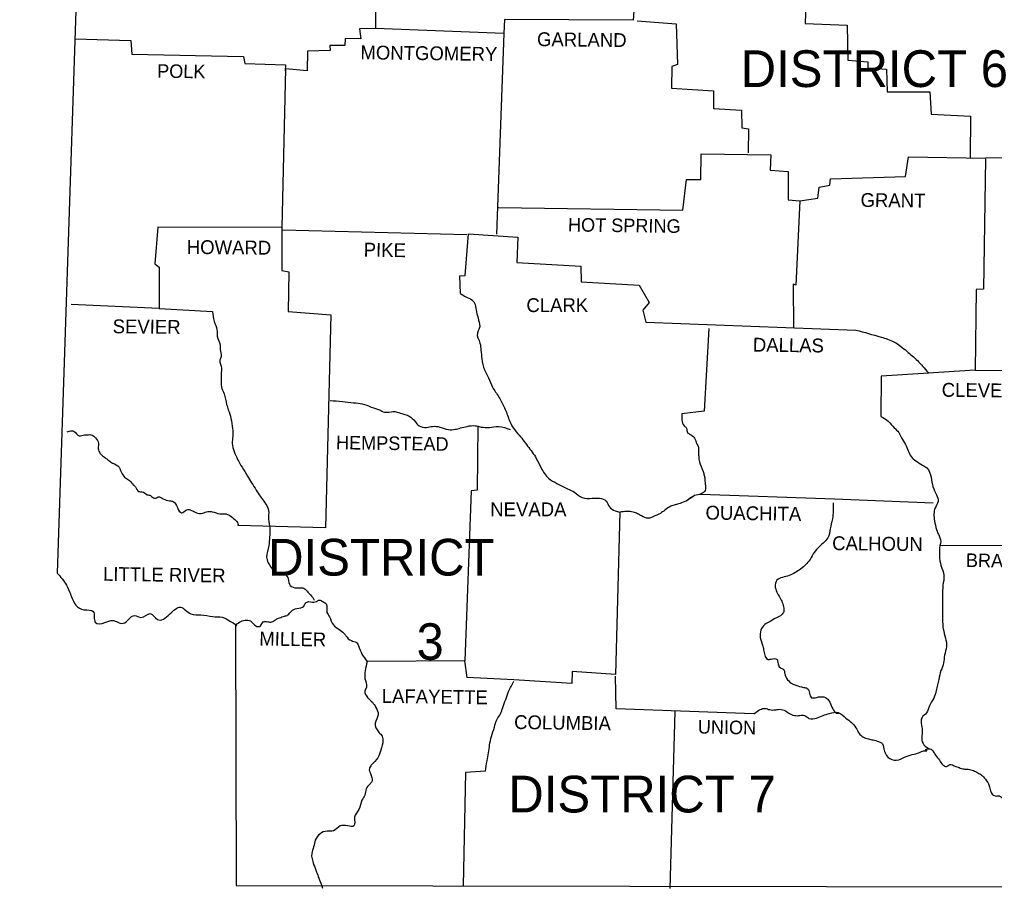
# Model space of a CAD drawing. Extents: x -42408 to 34530, y -43140 to 20491.
# Drawn here: x 1640 to 3155, y -35715 to -34364 of the extents above; entities that cross this region are included whole.
import ezdxf

# ---------------------------------------------------------------- set-up
doc = ezdxf.new("R2010")
doc.units = 0
for name, color, linetype in [('1', 7, 'Continuous'), ('2', 7, 'Continuous'), ('3', 7, 'Continuous')]:
    doc.layers.add(name, color=color, linetype=linetype)

msp = doc.modelspace()

# ---------------------------------------------------------------- linework, layer by layer
at = {"layer": '1'}
for points in [[(1640, -33034), (1743.7, -33866.1), (1698.6, -35224.4)], [(2194.3, -34085.9), (2193.3, -34378.7), (2168.2, -34379.2), (2170.2, -34394.3), (2146.2, -34393.8), (2145.7, -34404.8), (2122.2, -34404.8), (2122.7, -34412.8), (2087.6, -34413.8), (2087.1, -34444.3), (2053.1, -34441.3), (2047.6, -34687.7), (1854.8, -34687.2), (1850.3, -34744.2), (1857.3, -34749.2), (1856.8, -34813.3), (1720.1, -34807.3)], [(2762, -34306.2), (2598.3, -34301.1), (2593.8, -34365.7), (2393.5, -34364.7), (2392.5, -34386.3)], [(2806.6, -34304.6), (2862.7, -34308.2), (2860.6, -34370.7), (2926.2, -34373.2), (2927.2, -34427.8), (2958.3, -34430.3), (2958.3, -34439.8), (2987.3, -34441.8), (2988.3, -34476.9), (3054.4, -34476.9), (3056.4, -34511.4), (3117.5, -34514.4), (3117, -34579.5)], [(2599.8, -34366.7), (2660.4, -34371.2), (2662.4, -34434.3), (2653.9, -34437.3), (2652.9, -34470.9), (2718.5, -34475.4), (2718.5, -34502.9), (2762, -34505.4), (2762.5, -34533), (2773, -34534.5), (2772.5, -34571.5)], [(2392.5, -34386.3), (2193.3, -34378.7)], [(2392.5, -34386.3), (2381, -34698.2)], [(1726.1, -34394.3), (1812.8, -34397.3), (1814.8, -34418.3), (1988, -34421.8), (1990, -34432.8), (2053.1, -34434.8), (2052.6, -34444.3)], [(3714.3, -34521.9), (3525, -34516.9), (3524, -34578.5), (3141, -34580)], [(2384.5, -34656.6), (2670.9, -34660.6), (2676.4, -34613.1), (2698.9, -34613.1), (2699.4, -34573), (2807.6, -34574.5), (2806.6, -34598.5), (2834.6, -34600.5), (2834.6, -34644.6), (2852.6, -34646.1)], [(2852.6, -34646.1), (2880.7, -34642.1), (2882.7, -34625.1), (2899.2, -34622.1), (2900.2, -34612.1), (3016.9, -34608.6), (3021.4, -34578), (3141, -34580)], [(3141, -34581), (3138, -34783.3), (3126.5, -34783.8), (3125, -34909.5)], [(2852.6, -34646.1), (2846.6, -34777.3), (2842.1, -34775.8), (2842.6, -34843.9)], [(2047.6, -34687.7), (2047.6, -34754.2), (2058.6, -34756.3), (2057.6, -34818.3), (2123.7, -34823.3), (2115.7, -35154.3), (1979.5, -35150.8)], [(2048.6, -34691.2), (2334.9, -34698.7)], [(2325.4, -34790.3), (2324.4, -34762.8), (2332.4, -34762.3), (2337.5, -34697.7), (2414.6, -34702.7), (2412.6, -34742.2), (2512.2, -34747.7), (2512.7, -34771.8), (2602.8, -34777.3), (2618.3, -34804.3), (2608.8, -34816.3), (2613.3, -34834.9), (2939.8, -34846.9)], [(1856.8, -34813.3), (1939.9, -34818.3)], [(2711.4, -34844.4), (2703.9, -34973), (2669.4, -34977)], [(3052.9, -34914), (2978.8, -34918.5), (2978.3, -34981.1)], [(3125, -34909.5), (3051.9, -34914)], [(3125, -34909.5), (3302.2, -34910.5)], [(2352, -34996.1), (2351, -35095.7), (2342, -35096.7), (2331.9, -35360.6)], [(2698.9, -35101.7), (2906.2, -35109.2), (3059.9, -35115.2)], [(2572.8, -35129.8), (2566.3, -35382.1), (2498.7, -35377.6), (2498.2, -35396.1), (2408, -35390.6)], [(3069.9, -35181.8), (3296.2, -35181.3)], [(1975.5, -35305), (1976.5, -35710), (3811.4, -35713)], [(2408, -35390.6), (2335.4, -35386.6), (2331.9, -35360.6), (2180.2, -35362.1)], [(2781, -35443.2), (2567.3, -35435.2), (2566.3, -35384.6)], [(2658.4, -35439.7), (2650.4, -35714.5)], [(2364, -35532.3), (2332.9, -35534.3), (2329.4, -35710.5)]]:
    msp.add_lwpolyline(points, dxfattribs=at)
for points in [[(2325.4, -34790.3), (2333.4, -34795.3), (2343, -34799.8), (2348, -34807.3), (2350, -34818.8), (2353.5, -34831.4), (2354.5, -34844.4), (2351.5, -34851.4), (2355.5, -34867.4), (2357, -34878.4), (2358.5, -34891.4), (2362.5, -34909), (2369, -34921), (2375, -34935.5), (2385, -34951), (2393.5, -34968), (2397.5, -34977), (2405, -34995.6), (2414.6, -35008.1), (2429.6, -35027.1), (2443.1, -35046.6), (2450.6, -35061.2), (2462.1, -35077.2), (2475.1, -35085.2), (2491.7, -35093.7), (2502.2, -35098.7), (2514.2, -35107.2), (2529.7, -35108.2), (2541.2, -35108.2), (2551.7, -35112.7), (2556.7, -35121.7), (2565.8, -35127.7), (2572.8, -35129.8)], [(1939.9, -34818.3), (1942.4, -34833.4), (1946.9, -34846.4), (1947.4, -34856.4), (1951.9, -34871.4), (1951.9, -34876.9), (1953.4, -34887.9), (1951.4, -34893.9), (1953.9, -34906), (1953.4, -34915), (1953.4, -34922.5), (1953.9, -34935), (1957.9, -34946), (1961.9, -34962.5), (1964.5, -34971), (1968.5, -34984.1), (1971, -35000.1), (1971.5, -35012.1), (1970.5, -35023.1), (1973.5, -35035.6), (1979, -35048.1), (1986, -35060.2), (1994.5, -35073.7), (2000.5, -35084.2), (2008, -35095.7), (2014, -35105.2), (2023, -35117.2), (2027, -35127.2), (2027, -35141.3), (2029, -35154.3), (2028.5, -35168.8), (2027.5, -35181.8), (2024, -35199.8), (2026.5, -35208.4), (2036, -35220.9), (2042.1, -35224.4), (2052.6, -35226.4), (2057.6, -35233.4), (2060.6, -35243.9), (2071.1, -35247.4), (2082.6, -35248.4), (2088.1, -35254.4), (2095.6, -35262.4), (2098.1, -35266.4)], [(2939.8, -34846.9), (2978.8, -34857.9), (2998.8, -34865.4), (3018.9, -34879.9), (3035.4, -34894.4), (3051.9, -34913)], [(2122.7, -34956.5), (2141.7, -34958), (2159.2, -34960), (2172.7, -34961.5), (2186.7, -34966.5), (2199.3, -34971), (2207.3, -34974.5), (2220.8, -34973.5), (2232.3, -34976), (2245.3, -34980.6), (2254.8, -34989.1), (2260.8, -34995.6), (2272.4, -34998.1), (2281.9, -34996.6), (2293.4, -34997.6), (2306.4, -35001.6), (2316.9, -35001.1), (2325.4, -34999.1), (2335.4, -34996.6), (2348, -34995.6), (2357.5, -34997.6), (2370, -34998.1), (2384.5, -34996.6), (2402.5, -35001.6)], [(2669.4, -34977), (2669.4, -34986.6), (2672.9, -34995.6), (2676.4, -34999.6), (2677.9, -35006.1), (2682.4, -35009.1), (2688.9, -35015.1), (2692.4, -35023.6), (2694.9, -35029.1), (2694.9, -35036.1), (2695.4, -35043.1), (2696.4, -35051.6), (2702.4, -35066.7), (2703.9, -35072.7), (2704.9, -35077.7), (2705.4, -35086.2), (2705.4, -35096.2), (2698.9, -35101.7)], [(2978.3, -34981.1), (2989.8, -34988.6), (2999.3, -34998.6), (3006.3, -35006.1), (3010.8, -35014.6), (3016.9, -35024.6), (3025.4, -35043.6), (3032.9, -35050.1), (3043.4, -35056.7), (3049.9, -35061.2), (3056.4, -35075.7), (3059.4, -35090.2), (3064.9, -35103.2), (3067.4, -35113.2), (3062.9, -35123.2), (3061.9, -35143.3), (3064.9, -35156.8), (3068.9, -35166.8), (3071.4, -35178.3), (3069.9, -35181.8)], [(1714.1, -35005.1), (1725.1, -35004.6), (1732.6, -35011.1), (1737.1, -35010.6), (1745.2, -35009.6), (1752.7, -35010.1), (1758.2, -35014.6), (1762.7, -35022.6), (1762.2, -35030.1), (1762.7, -35033.1), (1766.2, -35039.6), (1772.2, -35044.6), (1778.7, -35049.6), (1784.7, -35053.6), (1794.7, -35060.2), (1795.7, -35062.2), (1799.7, -35070.2), (1804.7, -35076.7), (1810.7, -35080.7), (1817.3, -35087.7), (1820.3, -35090.7), (1825.3, -35097.7), (1830.8, -35098.2), (1838.3, -35102.7), (1843.8, -35104.2), (1849.8, -35108.2), (1855.8, -35106.2), (1863.3, -35109.2), (1873.3, -35112.2), (1878.8, -35113.2), (1885.3, -35122.7), (1891.9, -35130.8), (1899.9, -35126.2), (1914.9, -35130.8), (1924.4, -35131.3), (1932.9, -35128.7), (1939.4, -35129.2), (1951.4, -35132.3), (1958.9, -35132.3), (1967, -35135.3), (1974.5, -35141.3), (1979.5, -35147.8), (1979.5, -35150.8)], [(2676.4, -35112.2), (2689.4, -35103.7), (2698.9, -35101.7)], [(2689.4, -35103.7), (2676.4, -35112.2), (2666.4, -35116.2), (2658.9, -35118.7), (2651.9, -35120.7), (2642.9, -35126.7), (2635.8, -35131.8), (2626.3, -35136.3), (2617.3, -35139.3), (2606.3, -35135.8), (2600.3, -35132.3), (2593.8, -35129.8), (2572.8, -35129.8)], [(2904.2, -35115.2), (2903.2, -35140.3), (2899.7, -35155.8), (2896.2, -35169.8), (2888.7, -35177.8), (2880.7, -35185.8), (2873.2, -35194.8), (2866.7, -35205.9), (2860.1, -35212.9), (2851.6, -35219.9), (2843.1, -35224.9), (2833.6, -35229.4), (2823.1, -35231.9), (2815.6, -35237.4), (2815.1, -35249.4), (2823.6, -35266.4), (2826.6, -35274.4), (2827.6, -35284), (2824.1, -35289.5), (2816.1, -35294), (2806.6, -35299.5), (2798.1, -35304.5), (2792.1, -35313), (2791.1, -35324.5), (2795.1, -35338), (2796.6, -35346), (2803.1, -35358.6), (2808.1, -35358.1), (2817.1, -35358.6), (2818.1, -35361.1), (2818.6, -35363.6), (2820.6, -35370.1), (2828.1, -35375.6), (2829.1, -35380.6), (2833.6, -35390.1), (2841.1, -35396.6), (2846.6, -35398.6), (2858.1, -35402.1), (2864.2, -35403.6), (2870.7, -35418.1), (2878.7, -35417.6), (2884.7, -35416.6), (2894.7, -35419.1), (2899.2, -35425.1), (2903.7, -35435.2), (2909.7, -35442.2), (2913.7, -35442.2)], [(3069.9, -35181.8), (3071.9, -35212.9), (3076.4, -35227.9), (3074.9, -35243.9), (3074.4, -35259.4), (3074.4, -35273.4), (3074.4, -35287), (3074.4, -35301), (3075.4, -35311), (3078.9, -35325.5), (3080.4, -35339), (3077.4, -35352), (3075.9, -35364.1), (3071.9, -35376.1), (3068.4, -35389.6), (3064.4, -35407.1), (3060.9, -35418.6), (3053.9, -35430.7), (3049.4, -35441.7), (3042.4, -35448.7), (3041.4, -35460.7), (3042.9, -35471.7), (3041.9, -35481.7), (3045.4, -35491.2), (3054.4, -35497.7)], [(1698.6, -35224.4), (1713.1, -35243.4), (1719.1, -35256.9), (1727.6, -35274.4), (1740.2, -35281.5), (1754.7, -35284), (1757.7, -35301), (1772.7, -35301.5), (1784.7, -35298), (1801.2, -35302.5), (1818.8, -35290.5), (1828.8, -35293.5), (1843.3, -35287.5), (1854.3, -35296.5), (1873.3, -35288.5), (1890.4, -35277.4), (1906.4, -35288), (1921.9, -35289.5), (1940.4, -35292), (1954.9, -35293), (1968, -35299.5), (1977.5, -35306), (1975.5, -35305)], [(1975.5, -35305), (1993, -35297.5), (2000.5, -35300), (2007, -35306.5), (2014.5, -35306.5), (2018.5, -35300.5), (2026, -35300), (2032, -35300.5), (2038.6, -35296.5), (2044.1, -35294), (2051.6, -35291.5), (2057.1, -35289.5), (2062.1, -35284), (2071.1, -35279.5), (2081.6, -35275.9), (2084.6, -35270.9), (2089.6, -35268.9), (2099.6, -35269.4), (2106.1, -35266.4), (2111.6, -35268.9), (2116.7, -35272.4), (2117.7, -35285.5), (2121.7, -35292.5), (2127.7, -35305), (2136.2, -35311.5), (2144.2, -35318), (2147.2, -35322), (2155.7, -35329.5), (2163.2, -35332), (2166.7, -35337.5), (2172.2, -35350.5), (2180.2, -35362.1)], [(2180.2, -35362.1), (2177.2, -35376.6), (2176.7, -35388.1), (2179.2, -35401.6), (2176.7, -35408.1), (2180.7, -35417.6), (2188.3, -35425.1), (2193.8, -35433.2), (2197.3, -35444.7), (2192.8, -35457.7), (2197.8, -35471.2), (2202.3, -35476.2), (2204.8, -35484.2), (2201.3, -35499.7), (2196.8, -35511.3), (2186.7, -35522.8), (2183.7, -35528.3), (2185.2, -35535.8), (2187.8, -35547.8), (2185.2, -35551.3), (2178.7, -35559.8), (2176.7, -35569.3), (2172.2, -35577.3), (2167.2, -35591.9), (2160.7, -35603.9), (2159.7, -35617.4), (2149.7, -35617.4), (2138.2, -35617.4), (2127.7, -35624.9), (2118.2, -35625.4), (2106.6, -35629.9), (2099.6, -35639.4), (2097.1, -35649.9), (2094.1, -35660), (2097.1, -35677), (2101.6, -35689), (2105.1, -35698.5), (2111.1, -35714)], [(2364, -35532.3), (2366.5, -35516.3), (2369, -35503.7), (2370.5, -35491.7), (2373.5, -35478.2), (2378, -35463.7), (2382, -35451.7), (2387.5, -35443.2), (2391, -35433.2), (2395.5, -35421.1), (2400, -35408.6), (2408, -35392.6)], [(2781, -35443.2), (2789.1, -35437.7), (2796.6, -35434.7), (2804.1, -35436.2), (2812.1, -35437.2), (2819.1, -35436.2), (2828.1, -35437.7), (2835.6, -35442.2), (2844.1, -35445.7), (2852.6, -35445.7), (2860.1, -35445.7), (2866.7, -35450.2), (2878.7, -35449.7), (2888.7, -35445.7), (2898.7, -35442.7), (2912.2, -35441.2), (2924.2, -35449.7), (2932.7, -35456.7), (2939.8, -35464.7), (2944.8, -35473.7), (2950.3, -35478.7), (2959.3, -35482.2), (2966.3, -35483.7), (2974.8, -35486.2), (2979.3, -35488.2), (2983.3, -35497.7), (2989.8, -35510.8), (3002.3, -35515.3), (3017.9, -35509.3), (3030.4, -35505.8), (3039.4, -35502.7), (3044.9, -35500.7), (3049.9, -35500.2), (3048.4, -35499.2), (3054.4, -35497.7), (3059.9, -35501.7), (3063.4, -35507.3), (3069.4, -35515.3), (3074.9, -35522.3), (3080.4, -35524.8), (3085.9, -35521.8), (3093.5, -35524.3), (3100, -35526.8), (3107.5, -35528.8), (3114, -35529.3), (3122.5, -35531.3), (3129, -35534.8), (3135, -35538.3), (3141, -35544.8), (3147, -35554.8), (3149, -35562.8), (3156, -35570.8), (3162.6, -35570.8), (3172.1, -35583.9), (3175.6, -35588.9), (3183.1, -35597.9), (3188.6, -35597.9), (3199.1, -35599.9)]]:
    msp.add_spline(points, degree=3, dxfattribs=at)

# ---------------------------------------------------------------- texts
at = {"layer": '2'}
for s, height, rotation, p in [('GARLAND', 21.53, 359.3658, (2444.1, -34405.8)), ('MONTGOMERY', 21.53, 359.2944, (2169.7, -34426.3)), ('POLK', 21.02, 359.2152, (1853.8, -34454.9)), ('GRANT', 21.53, 359.4032, (2946.8, -34655.6)), ('HOT SPRING', 21.03, 359.2216, (2492.2, -34693.7)), ('HOWARD', 21.53, 359.5145, (1899.9, -34728.7)), ('PIKE', 21.52, 359.0452, (2174.7, -34732.7)), ('SEVIER', 21.53, 359.4271, (1784.7, -34851.9)), ('DALLAS', 21.52, 359.2462, (2779.5, -34880.4)), ('CLEVELAND', 21.53, 359.3377, (3072.9, -34950.5)), ('HEMPSTEAD', 21.02, 359.1885, (2131.7, -35032.1)), ('OUACHITA', 21.53, 359.2043, (2705.9, -35141.3)), ('CALHOUN', 21.53, 359.3634, (2902.7, -35188.8)), ('BRADLEY', 21.02, 359.1449, (3110.5, -35214.9)), ('LITTLE RIVER', 21.53, 359.1697, (1769.7, -35236.4)), ('MILLER', 21.52, 359.1319, (2012.5, -35337)), ('LAFAYETTE', 21.52, 359.1839, (2202.8, -35426.1)), ('COLUMBIA', 21.52, 359.2125, (2408.5, -35466.7)), ('UNION', 21.03, 358.9584, (2693.9, -35473.7))]:
    msp.add_text(s, height=height, rotation=rotation, dxfattribs=at).set_placement(p)
for s, p in [('CLARK', (2427.7, -34819)), ('NEVADA', (2371.5, -35136.3))]:
    msp.add_text(s, height=21.53, dxfattribs=at).set_placement(p)
at = {"layer": '3'}
for s, height, p in [('DISTRICT 6', 57.08, (2760.5, -34469.4)), ('DISTRICT', 57.08, (2026.3, -35228.4)), ('3', 56.6, (2257.1, -35359.1)), ('DISTRICT 7', 57.08, (2399.5, -35596.4))]:
    msp.add_text(s, height=height, dxfattribs=at).set_placement(p)

doc.saveas('drawing.dxf')
